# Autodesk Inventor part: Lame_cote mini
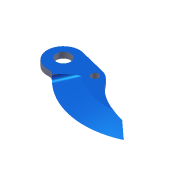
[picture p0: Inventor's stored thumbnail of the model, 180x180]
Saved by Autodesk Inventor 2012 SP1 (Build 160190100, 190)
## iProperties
Created: 2014-12
Part Number: Lame_cote mini
Material: Default
Document SubType Name: Modeling
Designer: Bruno
Density: 1 g/cm^3
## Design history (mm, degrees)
node "Lame_cote mini1"
node "Lame_cote mini"
node "Base1"
